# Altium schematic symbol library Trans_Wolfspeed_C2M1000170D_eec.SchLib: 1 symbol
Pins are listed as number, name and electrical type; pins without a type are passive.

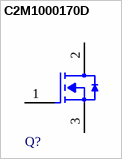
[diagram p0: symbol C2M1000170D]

## C2M1000170D
designator Q?  (value not drawn)
pins: 1 Gate, 2 Drain, 3 Source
